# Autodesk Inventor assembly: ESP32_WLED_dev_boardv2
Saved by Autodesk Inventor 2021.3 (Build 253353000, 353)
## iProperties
Created: 2022-06
Part Number: ESP32_WLED_dev_boardv2
Document SubType Name: Assembly
Designer: Administrator
Title: ESP32_WLED_dev_boardv2 v1
Author: Administrator
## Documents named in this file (8)
- c:\worker\convert-fusion-r03\tmp\job-1\203\output\files\98ba3c1f-9f0e-47fe-8659-38db50984f0d\088aeba6-40dc-4ff9-b089-b0cff28e2fc0.zip.iam
- c:\worker\convert-fusion-r03\tmp\job-1\203\output\files\98ba3c1f-9f0e-47fe-8659-38db50984f0d\SW_SPST_b3u-3000p-b.iam
- c:\worker\convert-fusion-r03\tmp\job-1\203\output\files\98ba3c1f-9f0e-47fe-8659-38db50984f0d\HF7520_005-HSTP.iam
- c:\worker\convert-fusion-r03\tmp\job-1\203\output\files\98ba3c1f-9f0e-47fe-8659-38db50984f0d\VXO78012-1000.iam
- c:\worker\convert-fusion-r03\tmp\job-1\203\output\files\98ba3c1f-9f0e-47fe-8659-38db50984f0d\Fuse_mini_holderXF-506.iam
- c:\worker\convert-fusion-r03\tmp\job-1\203\output\files\98ba3c1f-9f0e-47fe-8659-38db50984f0d\SO-16_3.9mm_P0.65.iam
- c:\worker\convert-fusion-r03\tmp\job-1\203\output\files\98ba3c1f-9f0e-47fe-8659-38db50984f0d\104031-0811.iam
- c:\worker\convert-fusion-r03\tmp\job-1\203\output\files\98ba3c1f-9f0e-47fe-8659-38db50984f0d\ESP32_WLED_dev_boardv2 PCB.ipt
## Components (8 placed, 7 different names)
1. SW_SPST_b3u-3000p-b:1 [sub-assembly]
2. HF7520_005-HSTP:1 [sub-assembly]
3. SW_SPST_b3u-3000p-b:2 [sub-assembly]
4. VXO78012-1000:1 [sub-assembly]
5. Fuse_mini_holderXF-506:1 [sub-assembly]
6. SO-16_3.9mm_P0.65:1 [sub-assembly]
7. 104031-0811:1 [sub-assembly]
8. ESP32_WLED_dev_boardv2 PCB:1
